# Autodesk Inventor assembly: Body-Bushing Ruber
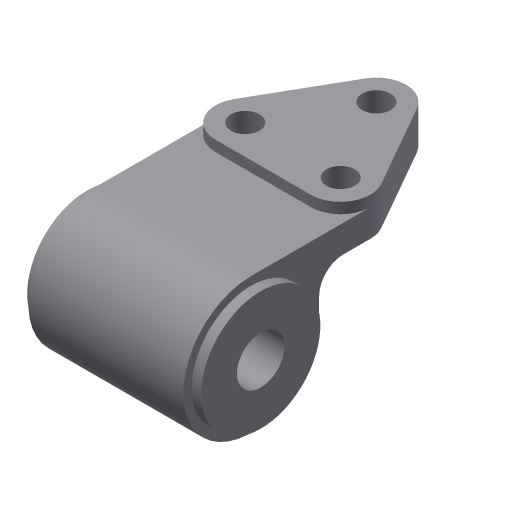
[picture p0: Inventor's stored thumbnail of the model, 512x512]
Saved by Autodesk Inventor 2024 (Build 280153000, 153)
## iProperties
Created: 2011-07
Part Number: Body-Bushing Ruber
Document SubType Name: Assembly
Designer: CadCim
Author: CadCim
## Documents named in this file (3)
- D:\PROJECTS\Project 2023\RESOURCES INVENTOR 2024\RESOURCES INVENTOR 2024\Inventor_2024_tut\Inventor_2024_tut\c09_Inv_2024_tut\c09_Inv_2024_tut\c09_Inv_tut_2024\c09_tut03_inv\Anti Vibration Mount\Body-Bushing Ruber.iam
- D:\PROJECTS\Project 2023\RESOURCES INVENTOR 2024\RESOURCES INVENTOR 2024\Inventor_2024_tut\Inventor_2024_tut\c09_Inv_2024_tut\c09_Inv_2024_tut\c09_Inv_tut_2024\c09_tut03_inv\Anti Vibration Mount\Body.ipt
- D:\PROJECTS\Project 2023\RESOURCES INVENTOR 2024\RESOURCES INVENTOR 2024\Inventor_2024_tut\Inventor_2024_tut\c09_Inv_2024_tut\c09_Inv_2024_tut\c09_Inv_tut_2024\c09_tut03_inv\Anti Vibration Mount\Bushing Rubber.ipt
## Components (3 placed, 2 different names)
1. Body:1 — Insert:1, Insert:2
2. Bushing Rubber:1 — Insert:1
3. Bushing Rubber:2 — Insert:2
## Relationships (2: Insert 2)
- Insert:1: Body:1 ↔ Bushing Rubber:1
- Insert:2: Body:1 ↔ Bushing Rubber:2
